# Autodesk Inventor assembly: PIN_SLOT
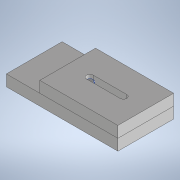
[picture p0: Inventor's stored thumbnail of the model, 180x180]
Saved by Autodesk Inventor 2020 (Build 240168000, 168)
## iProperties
Created: 2023-07
Part Number: PIN_SLOT
Document SubType Name: Assembly
Designer: chae-won
Author: chae-won
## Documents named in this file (4)
- C:\Users\chae-won\Desktop\설계도면\PIN_SLOT\PIN_SLOT-EX1.iam
- C:\Users\chae-won\Desktop\설계도면\PIN_SLOT\BASE.ipt
- C:\Users\chae-won\Desktop\설계도면\PIN_SLOT\PIN_8-12.ipt
- C:\Users\chae-won\Desktop\설계도면\PIN_SLOT\SLIDE.ipt
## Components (3 placed, 3 different names)
1. BASE:1 — 플러쉬:1, 플러쉬:3
2. PIN_8-12:1 — 플러쉬:1
3. SLIDE:1 — 플러쉬:3
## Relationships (2: Flush 2)
- 플러쉬:1 [Flush]: BASE:1 ↔ PIN_8-12:1
- 플러쉬:3 [Flush]: BASE:1 ↔ SLIDE:1
